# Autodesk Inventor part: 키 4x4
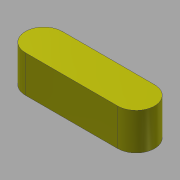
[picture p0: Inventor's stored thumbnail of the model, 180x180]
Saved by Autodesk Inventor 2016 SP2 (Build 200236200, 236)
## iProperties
Created: 2016-04
Part Number: 키 4x4
Document SubType Name: Modeling
Designer: mdu
Density: 7.86 g/cm^3
Mass: 1.65269 g
Surface Area: 2.35398 cm^2
Volume: 0.210265 cm^3
Material: 강철, 연강
Appearance: 강철 - 광택
Author: mdu
Revision Number: 1
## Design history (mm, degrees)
sketch "스케치1"
  geometry: L1 (-5, -2)-(5, -2); L2 (5, 2)-(-5, 2); A1 r 2 centre (5, 0) between (5, -2) and (5, 2); A2 r 2 centre (-5, 0) between (-5, 2) and (-5, -2); 2 further points
  constraints: 4 end point, 4 point on circle, 4 tangent, 2 centre point, 1 horizontal, 1 horizontal alignment, 1 midpoint, 1 parallel, 1 vertical alignment
  dimensions: "d0" = 4 distance between parallel lines of L1 L2; "d1" = 14 dimension on A1 A2
extrude "돌출1" new body sketch "스케치1" stored distance "d2" = 4; taper "d3" = 0 deg
node "솔리드1"
